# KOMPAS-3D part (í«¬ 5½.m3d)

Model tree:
1. Эскиз:1
2. Операция выдавливания:1
     Расстояние 1 = 2
3. Эскиз:2
4. Операция выдавливания:2
     Расстояние 1 = 5
5. Эскиз:3
6. Операция выдавливания:3
     Расстояние 1 = 2
7. Эскиз:4
8. Операция выдавливания:4
     Расстояние 1 = 60
9. Эскиз:5
10. Операция выдавливания:5
     Расстояние 1 = 2
11. Эскиз:6
12. Операция выдавливания:6
     Расстояние 1 = 4.5
13. Эскиз:7
14. Операция выдавливания:7
     Расстояние 1 = 2
15. Скругление:1
     Радиус = 1
16. Скругление:2
     Радиус = 1
17. Эскиз:8
18. Вырезать элемент выдавливания:1
     Расстояние 1 = 10; Угол 1 = 35
19. Эскиз:9
20. Вырезать элемент выдавливания:2
     Расстояние 1 = 10; Угол 1 = 35
21. Эскиз:10
22. Вырезать элемент выдавливания:3
     Расстояние 2 = 22; Расстояние 1 = 22; Угол 1 = 35
23. Эскиз:11
24. Вырезать элемент выдавливания:4
     Расстояние 2 = 2; Расстояние 1 = 2
25. Эскиз:12
26. Вырезать элемент выдавливания:5
     Расстояние 2 = 2; Расстояние 1 = 2; Угол 1 = 35
27. Эскиз:13
28. Вырезать элемент выдавливания:6
     Расстояние 2 = 2; Расстояние 1 = 122
29. Эскиз:15
30. Операция выдавливания:9
     Расстояние 1 = 10; Расстояние 2 = 0.5
